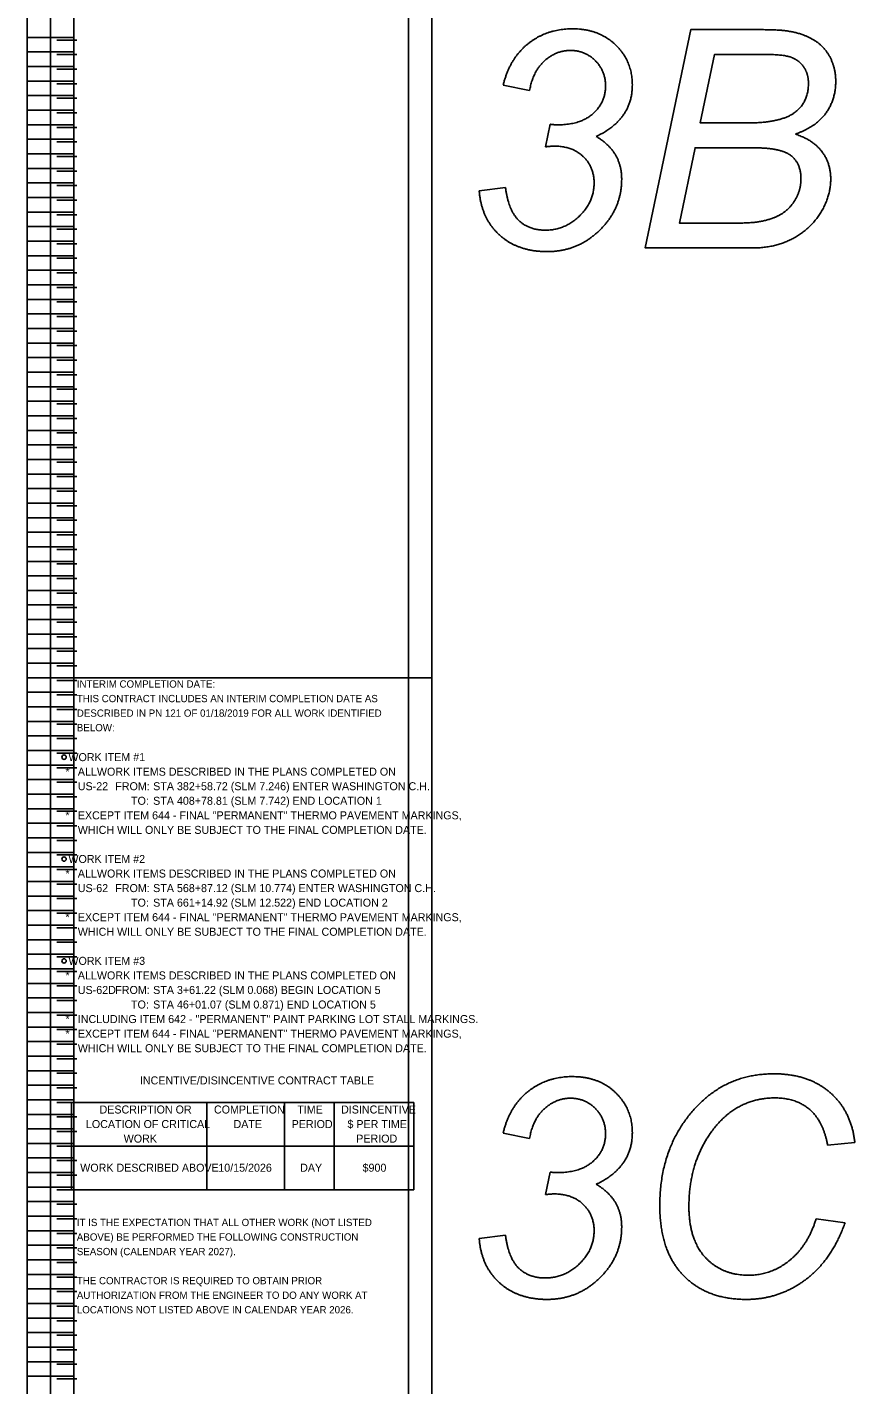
# Model space of a CAD drawing. Extents: x 12522 to 13018, y 1124 to 1902.
# Drawn here: x 12521.92 to 12537.85, y 1634.59 to 1660.71 of the extents above; entities that cross this region are included whole.
import ezdxf

# ---------------------------------------------------------------- set-up
doc = ezdxf.new("R2010")
doc.units = 0
for name, color, linetype in [('SC_Scratch1', 7, 'Continuous'), ('SH_Data', 7, 'Continuous'), ('SH_Text', 7, 'Continuous')]:
    doc.layers.add(name, color=color, linetype=linetype)

msp = doc.modelspace()

# ---------------------------------------------------------------- linework, layer by layer
at = {"layer": 'SC_Scratch1'}
for p, q in [((12521.919, 1648.191), (12521.919, 1668.351)), ((12522.819, 1648.191), (12522.819, 1668.351)), ((12522.819, 1668.351), (12522.819, 1648.191)), ((12521.919, 1660.511), (12522.819, 1660.511)), ((12522.876, 1660.461), (12522.492, 1660.461)), ((12521.919, 1660.231), (12522.819, 1660.231)), ((12522.876, 1660.181), (12522.492, 1660.181)), ((12521.919, 1659.951), (12522.819, 1659.951)), ((12522.876, 1659.901), (12522.492, 1659.901)), ((12521.919, 1659.671), (12522.819, 1659.671)), ((12522.876, 1659.621), (12522.492, 1659.621)), ((12531.591, 1659.488), (12531.082, 1659.591)), ((12521.919, 1659.391), (12522.819, 1659.391)), ((12522.876, 1659.341), (12522.492, 1659.341)), ((12521.919, 1659.111), (12522.819, 1659.111)), ((12522.876, 1659.061), (12522.492, 1659.061)), ((12521.919, 1658.831), (12522.819, 1658.831)), ((12531.896, 1658.407), (12531.985, 1658.841)), ((12521.919, 1658.551), (12522.819, 1658.551)), ((12522.876, 1658.781), (12522.492, 1658.781)), ((12522.876, 1658.501), (12522.492, 1658.501)), ((12521.919, 1658.271), (12522.819, 1658.271)), ((12522.876, 1658.221), (12522.492, 1658.221)), ((12521.919, 1657.991), (12522.819, 1657.991)), ((12522.876, 1657.941), (12522.492, 1657.941)), ((12521.919, 1657.711), (12522.819, 1657.711)), ((12522.876, 1657.661), (12522.492, 1657.661)), ((12530.621, 1657.562), (12531.127, 1657.626)), ((12521.919, 1657.431), (12522.819, 1657.431)), ((12522.876, 1657.381), (12522.492, 1657.381)), ((12521.919, 1657.151), (12522.819, 1657.151)), ((12522.876, 1657.101), (12522.492, 1657.101)), ((12521.919, 1656.871), (12522.819, 1656.871)), ((12522.876, 1656.821), (12522.492, 1656.821)), ((12521.919, 1656.591), (12522.819, 1656.591)), ((12522.876, 1656.541), (12522.492, 1656.541)), ((12521.919, 1656.311), (12522.819, 1656.311)), ((12522.876, 1656.261), (12522.492, 1656.261)), ((12521.919, 1656.031), (12522.819, 1656.031)), ((12522.876, 1655.981), (12522.492, 1655.981)), ((12521.919, 1655.751), (12522.819, 1655.751)), ((12522.876, 1655.701), (12522.492, 1655.701)), ((12521.919, 1655.471), (12522.819, 1655.471)), ((12522.876, 1655.421), (12522.492, 1655.421)), ((12521.919, 1655.191), (12522.819, 1655.191)), ((12522.876, 1655.141), (12522.492, 1655.141)), ((12521.919, 1654.911), (12522.819, 1654.911)), ((12521.919, 1654.631), (12522.819, 1654.631)), ((12522.876, 1654.861), (12522.492, 1654.861)), ((12522.876, 1654.581), (12522.492, 1654.581)), ((12521.919, 1654.351), (12522.819, 1654.351)), ((12522.876, 1654.301), (12522.492, 1654.301)), ((12521.919, 1654.071), (12522.819, 1654.071)), ((12522.876, 1654.021), (12522.492, 1654.021)), ((12521.919, 1653.791), (12522.819, 1653.791)), ((12522.876, 1653.741), (12522.492, 1653.741)), ((12521.919, 1653.511), (12522.819, 1653.511)), ((12522.876, 1653.461), (12522.492, 1653.461)), ((12521.919, 1653.231), (12522.819, 1653.231)), ((12522.876, 1653.181), (12522.492, 1653.181)), ((12521.919, 1652.951), (12522.819, 1652.951)), ((12522.876, 1652.901), (12522.492, 1652.901)), ((12521.919, 1652.671), (12522.819, 1652.671)), ((12522.876, 1652.621), (12522.492, 1652.621)), ((12521.919, 1652.391), (12522.819, 1652.391)), ((12522.876, 1652.341), (12522.492, 1652.341)), ((12521.919, 1652.111), (12522.819, 1652.111)), ((12522.876, 1652.061), (12522.492, 1652.061)), ((12521.919, 1651.831), (12522.819, 1651.831)), ((12522.876, 1651.781), (12522.492, 1651.781)), ((12521.919, 1651.551), (12522.819, 1651.551)), ((12522.876, 1651.501), (12522.492, 1651.501)), ((12521.919, 1651.271), (12522.819, 1651.271)), ((12522.876, 1651.221), (12522.492, 1651.221)), ((12521.919, 1650.991), (12522.819, 1650.991)), ((12521.919, 1650.711), (12522.819, 1650.711)), ((12522.876, 1650.941), (12522.492, 1650.941)), ((12522.876, 1650.661), (12522.492, 1650.661)), ((12521.919, 1650.431), (12522.819, 1650.431)), ((12522.876, 1650.381), (12522.492, 1650.381)), ((12521.919, 1650.151), (12522.819, 1650.151)), ((12522.876, 1650.101), (12522.492, 1650.101)), ((12521.919, 1649.871), (12522.819, 1649.871)), ((12522.876, 1649.821), (12522.492, 1649.821)), ((12521.919, 1649.591), (12522.819, 1649.591)), ((12522.876, 1649.541), (12522.492, 1649.541)), ((12521.919, 1649.311), (12522.819, 1649.311)), ((12522.876, 1649.261), (12522.492, 1649.261)), ((12521.919, 1649.031), (12522.819, 1649.031)), ((12522.876, 1648.981), (12522.492, 1648.981)), ((12521.919, 1648.751), (12522.819, 1648.751)), ((12522.876, 1648.701), (12522.492, 1648.701)), ((12521.919, 1648.471), (12522.819, 1648.471)), ((12522.876, 1648.421), (12522.492, 1648.421)), ((12521.919, 1648.191), (12522.819, 1648.191)), ((12521.919, 1628.031), (12521.919, 1648.191)), ((12521.919, 1648.191), (12522.819, 1648.191)), ((12522.876, 1648.141), (12522.492, 1648.141)), ((12522.819, 1628.031), (12522.819, 1648.191)), ((12522.819, 1648.191), (12522.819, 1628.031)), ((12521.919, 1647.911), (12522.819, 1647.911)), ((12522.876, 1647.861), (12522.492, 1647.861)), ((12521.919, 1647.631), (12522.819, 1647.631)), ((12522.876, 1647.581), (12522.492, 1647.581)), ((12521.919, 1647.351), (12522.819, 1647.351)), ((12522.876, 1647.301), (12522.492, 1647.301)), ((12521.919, 1647.071), (12522.819, 1647.071)), ((12521.919, 1646.791), (12522.819, 1646.791)), ((12522.876, 1647.021), (12522.492, 1647.021)), ((12522.876, 1646.741), (12522.492, 1646.741)), ((12521.919, 1646.511), (12522.819, 1646.511)), ((12522.876, 1646.461), (12522.492, 1646.461)), ((12521.919, 1646.231), (12522.819, 1646.231)), ((12522.876, 1646.181), (12522.492, 1646.181)), ((12521.919, 1645.951), (12522.819, 1645.951)), ((12522.876, 1645.901), (12522.492, 1645.901)), ((12521.919, 1645.671), (12522.819, 1645.671)), ((12522.876, 1645.621), (12522.492, 1645.621)), ((12521.919, 1645.391), (12522.819, 1645.391)), ((12522.876, 1645.341), (12522.492, 1645.341)), ((12521.919, 1645.111), (12522.819, 1645.111)), ((12522.876, 1645.061), (12522.492, 1645.061)), ((12521.919, 1644.831), (12522.819, 1644.831)), ((12522.876, 1644.781), (12522.492, 1644.781)), ((12521.919, 1644.551), (12522.819, 1644.551)), ((12522.876, 1644.501), (12522.492, 1644.501)), ((12521.919, 1644.271), (12522.819, 1644.271)), ((12522.876, 1644.221), (12522.492, 1644.221)), ((12521.919, 1643.991), (12522.819, 1643.991)), ((12522.876, 1643.941), (12522.492, 1643.941)), ((12521.919, 1643.711), (12522.819, 1643.711)), ((12522.876, 1643.661), (12522.492, 1643.661)), ((12521.919, 1643.431), (12522.819, 1643.431)), ((12521.919, 1643.151), (12522.819, 1643.151)), ((12522.876, 1643.381), (12522.492, 1643.381)), ((12521.919, 1642.871), (12522.819, 1642.871)), ((12522.876, 1643.101), (12522.492, 1643.101)), ((12522.876, 1642.821), (12522.492, 1642.821)), ((12521.919, 1642.591), (12522.819, 1642.591)), ((12522.876, 1642.541), (12522.492, 1642.541)), ((12521.919, 1642.311), (12522.819, 1642.311)), ((12522.876, 1642.261), (12522.492, 1642.261)), ((12521.919, 1642.031), (12522.819, 1642.031)), ((12522.876, 1641.981), (12522.492, 1641.981)), ((12521.919, 1641.751), (12522.819, 1641.751)), ((12522.876, 1641.701), (12522.492, 1641.701)), ((12521.919, 1641.471), (12522.819, 1641.471)), ((12522.876, 1641.421), (12522.492, 1641.421)), ((12521.919, 1641.191), (12522.819, 1641.191)), ((12522.876, 1641.141), (12522.492, 1641.141)), ((12521.919, 1640.911), (12522.819, 1640.911)), ((12522.876, 1640.861), (12522.492, 1640.861)), ((12521.919, 1640.631), (12522.819, 1640.631)), ((12522.876, 1640.581), (12522.492, 1640.581)), ((12521.919, 1640.351), (12522.819, 1640.351)), ((12522.876, 1640.301), (12522.492, 1640.301)), ((12521.919, 1640.071), (12522.819, 1640.071)), ((12522.876, 1640.021), (12522.492, 1640.021)), ((12521.919, 1639.791), (12522.819, 1639.791)), ((12522.876, 1639.741), (12522.492, 1639.741)), ((12521.919, 1639.511), (12522.819, 1639.511)), ((12521.919, 1639.231), (12522.819, 1639.231)), ((12522.876, 1639.461), (12522.492, 1639.461)), ((12531.591, 1639.328), (12531.082, 1639.431)), ((12537.852, 1639.249), (12537.327, 1639.201)), ((12521.919, 1638.951), (12522.819, 1638.951)), ((12522.876, 1639.181), (12522.492, 1639.181)), ((12522.876, 1638.901), (12522.492, 1638.901)), ((12531.896, 1638.247), (12531.985, 1638.681)), ((12521.919, 1638.671), (12522.819, 1638.671)), ((12522.876, 1638.621), (12522.492, 1638.621)), ((12521.919, 1638.391), (12522.819, 1638.391)), ((12522.876, 1638.341), (12522.492, 1638.341)), ((12521.919, 1638.111), (12522.819, 1638.111)), ((12522.876, 1638.061), (12522.492, 1638.061)), ((12521.919, 1637.831), (12522.819, 1637.831)), ((12522.876, 1637.781), (12522.492, 1637.781)), ((12537.107, 1637.78), (12537.664, 1637.703)), ((12521.919, 1637.551), (12522.819, 1637.551)), ((12522.876, 1637.501), (12522.492, 1637.501)), ((12530.621, 1637.402), (12531.127, 1637.466)), ((12521.919, 1637.271), (12522.819, 1637.271)), ((12522.876, 1637.221), (12522.492, 1637.221)), ((12521.919, 1636.991), (12522.819, 1636.991)), ((12522.876, 1636.941), (12522.492, 1636.941)), ((12521.919, 1636.711), (12522.819, 1636.711)), ((12522.876, 1636.661), (12522.492, 1636.661)), ((12521.919, 1636.431), (12522.819, 1636.431)), ((12522.876, 1636.381), (12522.492, 1636.381)), ((12521.919, 1636.151), (12522.819, 1636.151)), ((12522.876, 1636.101), (12522.492, 1636.101)), ((12521.919, 1635.871), (12522.819, 1635.871)), ((12522.876, 1635.821), (12522.492, 1635.821)), ((12521.919, 1635.591), (12522.819, 1635.591)), ((12521.919, 1635.311), (12522.819, 1635.311)), ((12522.876, 1635.541), (12522.492, 1635.541)), ((12521.919, 1635.031), (12522.819, 1635.031)), ((12522.876, 1635.261), (12522.492, 1635.261)), ((12522.876, 1634.981), (12522.492, 1634.981)), ((12521.919, 1634.751), (12522.819, 1634.751)), ((12522.876, 1634.701), (12522.492, 1634.701))]:
    msp.add_line(p, q, dxfattribs=at)
for points in [[(12522.369, 1668.351), (12529.709, 1668.351), (12529.709, 1648.191), (12522.369, 1648.191)], [(12522.819, 1668.351), (12529.259, 1668.351), (12529.259, 1648.191), (12522.819, 1648.191)], [(12522.369, 1648.191), (12529.709, 1648.191), (12529.709, 1628.031), (12522.369, 1628.031)], [(12522.819, 1648.191), (12529.259, 1648.191), (12529.259, 1628.031), (12522.819, 1628.031)]]:
    msp.add_lwpolyline(points, close=True, dxfattribs=at)
for points in [[(12536.034, 1660.661), (12534.693, 1660.661), (12533.816, 1656.461), (12535.897, 1656.461)], [(12535.771, 1658.865), (12534.877, 1658.865), (12535.152, 1660.184), (12536.09, 1660.184)], [(12535.467, 1656.938), (12534.474, 1656.938), (12534.777, 1658.388), (12535.893, 1658.388)]]:
    msp.add_lwpolyline(points, dxfattribs=at)
for points in [[(12531.566, 1660.393), (12531.924, 1660.677), (12532.414, 1660.677)], [(12532.414, 1660.677), (12532.93, 1660.677), (12533.25, 1660.365)], [(12536.577, 1660.632), (12536.4, 1660.661), (12536.034, 1660.661)], [(12537.066, 1660.461), (12536.867, 1660.583), (12536.577, 1660.632)], [(12531.082, 1659.591), (12531.208, 1660.11), (12531.566, 1660.393)], [(12533.25, 1660.365), (12533.569, 1660.052), (12533.569, 1659.597)], [(12537.375, 1660.129), (12537.266, 1660.34), (12537.066, 1660.461)], [(12532.377, 1660.261), (12532.099, 1660.261), (12531.876, 1660.059)], [(12532.857, 1660.063), (12532.661, 1660.261), (12532.377, 1660.261)], [(12536.09, 1660.184), (12536.493, 1660.184), (12536.639, 1660.125)], [(12536.639, 1660.125), (12536.785, 1660.066), (12536.872, 1659.937)], [(12537.484, 1659.663), (12537.484, 1659.918), (12537.375, 1660.129)], [(12531.876, 1660.059), (12531.654, 1659.857), (12531.591, 1659.488)], [(12533.054, 1659.577), (12533.054, 1659.866), (12532.857, 1660.063)], [(12536.872, 1659.937), (12536.959, 1659.807), (12536.959, 1659.629)], [(12533.569, 1659.597), (12533.569, 1659.265), (12533.395, 1659.017)], [(12536.959, 1659.629), (12536.959, 1659.256), (12536.686, 1659.06)], [(12537.293, 1659.052), (12537.484, 1659.316), (12537.484, 1659.663)], [(12532.813, 1659.046), (12533.054, 1659.262), (12533.054, 1659.577)], [(12536.686, 1659.06), (12536.413, 1658.865), (12535.771, 1658.865)], [(12531.985, 1658.841), (12532.059, 1658.83), (12532.128, 1658.83)], [(12532.128, 1658.83), (12532.572, 1658.83), (12532.813, 1659.046)], [(12533.395, 1659.017), (12533.221, 1658.77), (12532.874, 1658.606)], [(12536.707, 1658.651), (12537.101, 1658.788), (12537.293, 1659.052)], [(12532.874, 1658.606), (12533.121, 1658.46), (12533.243, 1658.254)], [(12537.219, 1658.314), (12537.049, 1658.539), (12536.707, 1658.651)], [(12532.062, 1658.42), (12532.022, 1658.42), (12531.896, 1658.407)], [(12532.624, 1658.218), (12532.415, 1658.42), (12532.062, 1658.42)], [(12535.893, 1658.388), (12536.437, 1658.388), (12536.626, 1658.235)], [(12537.388, 1657.789), (12537.388, 1658.09), (12537.219, 1658.314)], [(12532.833, 1657.707), (12532.833, 1658.017), (12532.624, 1658.218)], [(12533.243, 1658.254), (12533.364, 1658.048), (12533.364, 1657.782)], [(12536.626, 1658.235), (12536.815, 1658.082), (12536.815, 1657.787)], [(12533.364, 1657.782), (12533.364, 1657.218), (12532.942, 1656.804)], [(12536.815, 1657.787), (12536.815, 1657.59), (12536.717, 1657.41)], [(12537.185, 1657.125), (12537.388, 1657.443), (12537.388, 1657.789)], [(12531.012, 1656.71), (12530.661, 1657.029), (12530.621, 1657.562)], [(12531.127, 1657.626), (12531.184, 1657.185), (12531.38, 1656.994)], [(12532.554, 1657.078), (12532.833, 1657.353), (12532.833, 1657.707)], [(12536.717, 1657.41), (12536.619, 1657.23), (12536.447, 1657.119)], [(12531.38, 1656.994), (12531.575, 1656.803), (12531.893, 1656.803)], [(12531.893, 1656.803), (12532.276, 1656.803), (12532.554, 1657.078)], [(12536.447, 1657.119), (12536.275, 1657.009), (12535.998, 1656.964)], [(12536.645, 1656.634), (12536.981, 1656.807), (12537.185, 1657.125)], [(12531.932, 1656.39), (12531.363, 1656.39), (12531.012, 1656.71)], [(12532.942, 1656.804), (12532.519, 1656.39), (12531.932, 1656.39)], [(12535.998, 1656.964), (12535.862, 1656.938), (12535.467, 1656.938)], [(12535.897, 1656.461), (12536.31, 1656.461), (12536.645, 1656.634)], [(12531.566, 1640.233), (12531.924, 1640.517), (12532.414, 1640.517)], [(12532.414, 1640.517), (12532.93, 1640.517), (12533.25, 1640.205)], [(12534.78, 1639.91), (12535.387, 1640.571), (12536.29, 1640.571)], [(12536.29, 1640.571), (12536.958, 1640.571), (12537.372, 1640.213)], [(12531.082, 1639.431), (12531.208, 1639.95), (12531.566, 1640.233)], [(12532.377, 1640.101), (12532.099, 1640.101), (12531.876, 1639.899)], [(12532.857, 1639.903), (12532.661, 1640.101), (12532.377, 1640.101)], [(12533.25, 1640.205), (12533.569, 1639.892), (12533.569, 1639.437)], [(12536.316, 1640.107), (12535.545, 1640.107), (12535.069, 1639.423)], [(12536.984, 1639.882), (12536.725, 1640.107), (12536.316, 1640.107)], [(12537.372, 1640.213), (12537.786, 1639.854), (12537.852, 1639.249)], [(12531.876, 1639.899), (12531.654, 1639.697), (12531.591, 1639.328)], [(12533.054, 1639.417), (12533.054, 1639.706), (12532.857, 1639.903)], [(12534.097, 1638.034), (12534.097, 1639.168), (12534.78, 1639.91)], [(12537.327, 1639.201), (12537.244, 1639.657), (12536.984, 1639.882)], [(12532.813, 1638.886), (12533.054, 1639.102), (12533.054, 1639.417)], [(12533.569, 1639.437), (12533.569, 1639.105), (12533.395, 1638.857)], [(12535.069, 1639.423), (12534.658, 1638.833), (12534.658, 1638.023)], [(12531.985, 1638.681), (12532.059, 1638.67), (12532.128, 1638.67)], [(12532.128, 1638.67), (12532.572, 1638.67), (12532.813, 1638.886)], [(12533.395, 1638.857), (12533.221, 1638.61), (12532.874, 1638.446)], [(12532.874, 1638.446), (12533.121, 1638.3), (12533.243, 1638.094)], [(12532.062, 1638.26), (12532.022, 1638.26), (12531.896, 1638.247)], [(12532.624, 1638.058), (12532.415, 1638.26), (12532.062, 1638.26)], [(12532.833, 1637.547), (12532.833, 1637.857), (12532.624, 1638.058)], [(12533.243, 1638.094), (12533.364, 1637.888), (12533.364, 1637.622)], [(12534.546, 1636.697), (12534.097, 1637.164), (12534.097, 1638.034)], [(12534.658, 1638.023), (12534.658, 1637.376), (12534.976, 1637.035)], [(12536.593, 1636.978), (12536.946, 1637.262), (12537.107, 1637.78)], [(12537.664, 1637.703), (12537.4, 1636.975), (12536.895, 1636.603)], [(12531.012, 1636.55), (12530.661, 1636.869), (12530.621, 1637.402)], [(12531.127, 1637.466), (12531.184, 1637.025), (12531.38, 1636.834)], [(12532.554, 1636.918), (12532.833, 1637.193), (12532.833, 1637.547)], [(12533.364, 1637.622), (12533.364, 1637.058), (12532.942, 1636.644)], [(12531.893, 1636.643), (12532.276, 1636.643), (12532.554, 1636.918)], [(12534.976, 1637.035), (12535.294, 1636.695), (12535.805, 1636.695)], [(12535.805, 1636.695), (12536.24, 1636.695), (12536.593, 1636.978)], [(12531.38, 1636.834), (12531.575, 1636.643), (12531.893, 1636.643)], [(12532.942, 1636.644), (12532.519, 1636.23), (12531.932, 1636.23)], [(12535.761, 1636.23), (12534.995, 1636.23), (12534.546, 1636.697)], [(12536.895, 1636.603), (12536.39, 1636.23), (12535.761, 1636.23)], [(12531.932, 1636.23), (12531.363, 1636.23), (12531.012, 1636.55)]]:
    msp.add_open_spline(points, degree=2, dxfattribs=at)
at = {"layer": 'SH_Data'}
for p, q in [((12522.775, 1640.021), (12529.363, 1640.021)), ((12522.775, 1640.021), (12522.775, 1638.341)), ((12525.377, 1640.021), (12525.377, 1638.341)), ((12526.876, 1640.021), (12526.876, 1638.341)), ((12527.831, 1640.021), (12527.831, 1638.341)), ((12529.363, 1640.021), (12529.363, 1638.341)), ((12522.775, 1639.181), (12529.363, 1639.181)), ((12522.775, 1638.341), (12529.363, 1638.341))]:
    msp.add_line(p, q, dxfattribs=at)
for centre in [(12522.63, 1646.663), (12522.63, 1644.703), (12522.63, 1642.743)]:
    msp.add_circle(centre, 0.0426, dxfattribs=at)

# ---------------------------------------------------------------- texts
for s, p in [('INTERIM COMPLETION DATE:', (12522.876, 1648.001)), ('THIS CONTRACT INCLUDES AN INTERIM COMPLETION DATE AS ', (12522.876, 1647.721)), ('DESCRIBED IN PN 121 OF 01/18/2019 FOR ALL WORK IDENTIFIED ', (12522.876, 1647.441)), ('BELOW:', (12522.876, 1647.161)), ('IT IS THE EXPECTATION THAT ALL OTHER WORK (NOT LISTED ', (12522.876, 1637.641)), ('ABOVE) BE PERFORMED THE FOLLOWING CONSTRUCTION ', (12522.876, 1637.361)), ('SEASON (CALENDAR YEAR 2027).', (12522.876, 1637.081)), ('THE CONTRACTOR IS REQUIRED TO OBTAIN PRIOR ', (12522.876, 1636.521)), ('AUTHORIZATION FROM THE ENGINEER TO DO ANY WORK AT ', (12522.876, 1636.241)), ('LOCATIONS NOT LISTED ABOVE IN CALENDAR YEAR 2026.', (12522.876, 1635.961))]:
    msp.add_text(s, height=0.14, dxfattribs=at).set_placement(p)
at = {"layer": 'SH_Text'}
for s, p in [('WORK ITEM #1', (12522.714, 1646.587)), ('*', (12522.657, 1646.307)), ('ALL', (12522.895, 1646.307)), (' WORK ITEMS DESCRIBED IN THE PLANS COMPLETED ON', (12523.205, 1646.307)), ('US-22', (12522.895, 1646.027)), ('FROM:', (12523.616, 1646.027)), ('STA 382+58.72 (SLM 7.246) ENTER WASHINGTON C.H.', (12524.345, 1646.027)), ('TO:', (12523.919, 1645.747)), ('STA 408+78.81 (SLM 7.742) END LOCATION 1', (12524.345, 1645.747)), ('*', (12522.657, 1645.467)), ('EXCEPT ITEM 644 - FINAL "PERMANENT" THERMO PAVEMENT MARKINGS,', (12522.895, 1645.467)), ('WHICH WILL ONLY BE SUBJECT TO THE FINAL COMPLETION DATE.', (12522.895, 1645.187)), ('WORK ITEM #2', (12522.714, 1644.627)), ('*', (12522.657, 1644.347)), ('ALL', (12522.895, 1644.347)), (' WORK ITEMS DESCRIBED IN THE PLANS COMPLETED ON', (12523.205, 1644.347)), ('US-62', (12522.895, 1644.067)), ('FROM:', (12523.616, 1644.067)), ('STA 568+87.12 (SLM 10.774) ENTER WASHINGTON C.H.', (12524.345, 1644.067)), ('TO:', (12523.919, 1643.787)), ('STA 661+14.92 (SLM 12.522) END LOCATION 2', (12524.345, 1643.787)), ('*', (12522.657, 1643.507)), ('EXCEPT ITEM 644 - FINAL "PERMANENT" THERMO PAVEMENT MARKINGS,', (12522.895, 1643.507)), ('WHICH WILL ONLY BE SUBJECT TO THE FINAL COMPLETION DATE.', (12522.895, 1643.227)), ('WORK ITEM #3', (12522.714, 1642.667)), ('*', (12522.657, 1642.387)), ('ALL', (12522.895, 1642.387)), (' WORK ITEMS DESCRIBED IN THE PLANS COMPLETED ON', (12523.205, 1642.387)), ('US-62D', (12522.895, 1642.107)), ('FROM:', (12523.616, 1642.107)), ('STA 3+61.22 (SLM 0.068) BEGIN LOCATION 5', (12524.345, 1642.107)), ('TO:', (12523.919, 1641.827)), ('STA 46+01.07 (SLM 0.871) END LOCATION 5', (12524.345, 1641.827)), ('*', (12522.657, 1641.547)), ('INCLUDING ITEM 642 - "PERMANENT" PAINT PARKING LOT STALL MARKINGS.', (12522.895, 1641.547)), ('*', (12522.657, 1641.267)), ('EXCEPT ITEM 644 - FINAL "PERMANENT" THERMO PAVEMENT MARKINGS,', (12522.895, 1641.267)), ('WHICH WILL ONLY BE SUBJECT TO THE FINAL COMPLETION DATE.', (12522.895, 1640.987)), ('INCENTIVE/DISINCENTIVE CONTRACT TABLE', (12524.09, 1640.367)), ('DESCRIPTION OR', (12523.313, 1639.807)), ('COMPLETION', (12525.516, 1639.807)), ('TIME', (12527.119, 1639.807)), ('DISINCENTIVE', (12527.962, 1639.807)), ('LOCATION OF CRITICAL', (12523.051, 1639.527)), ('DATE', (12525.892, 1639.527)), ('PERIOD', (12527.011, 1639.527)), ('$ PER TIME', (12528.085, 1639.527)), ('WORK', (12523.778, 1639.247)), ('PERIOD', (12528.254, 1639.247)), ('WORK DESCRIBED ABOVE', (12522.941, 1638.687)), ('10/15/2026', (12525.599, 1638.687)), ('DAY', (12527.174, 1638.687)), ('$900', (12528.376, 1638.687))]:
    msp.add_text(s, height=0.154, dxfattribs=at).set_placement(p)

doc.saveas('drawing.dxf')
